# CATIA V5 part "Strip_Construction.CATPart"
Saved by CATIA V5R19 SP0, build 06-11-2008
Part number: Strip_Construction
Bounding box of the stored display mesh (mm): x -31.588 to 851.192, y -98.967 to 61.033, z -30.833 to 220
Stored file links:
  C:\Documents and Settings\drq\Desktop\Final_Data\Strip_Construction.CATPart
  C:\Documents and Settings\drq\Desktop\Final_Data\Worked_Part.CATPart
  C:\Documents and Settings\drq\Desktop\Strip_Construction123.CATPart
  C:\Program Files\Dassault Systemes\Strip Layout Design\intel_a\resources\graphic\Powercopies\PowerCopy_PunchAssociated.CATPart
  C:\Documents and Settings\drq\Desktop\Final_Data\Part_for_Strip.CATPart
  C:\Program Files\Dassault Systemes\Strip Layout Design\intel_a\resources\graphic\Powercopies\ISPSL9UDFCentering.CATPart
  C:\Program Files\Dassault Systemes\Strip Layout Design\intel_a\resources\graphic\Powercopies\UDF-PunchSimulation.CATPart
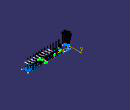
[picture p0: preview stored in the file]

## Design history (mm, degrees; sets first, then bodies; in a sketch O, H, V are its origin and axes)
Parameters
  Step_Length = 55 mm {= External.Step_Length}
  Strip_Width = 120 mm {= External.Strip_Width}
  Nb_Step = 12 {= External.Number_Of_Steps}
  Part_Thickness = 2 mm {= External.Part_Thickness}
  COG_X = 0 mm
  COG_Y = 0 mm
  COG_Z = 0 mm
  group "PunchFoce_Parameters"
    PunchContourArea = 659.1274 mm
    TotalPunchForce = 527302 (force)
    Rupture_Traction_Resistance_Coef = 4e+08 (pressure)
  Station1_FreeStep = 0
  Station2_FreeStep = 0
  Station3_FreeStep = 0
  Station4_FreeStep = 0
  Station5_FreeStep = 0
  Station6_FreeStep = 0
  Station7_FreeStep = 0
  Station8_FreeStep = 0
  Station9_FreeStep = 0
  Station10_FreeStep = 0
External parameters (linked from other documents)
  External.Step_Length = 55 mm
  External.Number_Of_Steps = 12
  External.Strip_Width = 120 mm
  External.Rotation_Part = 60 deg
  External.Part_Thickness = 2 mm
SheetMetalParameters1: BendRadius 4 {= 2*External.Part_Thickness}, ReliefAxialLength 2, ReliefRadialLength 1, MinimumBendRadius 0, Thickness 2 {= External.Part_Thickness}, KFactor 0.400515 {= log(min(100,max(20*SheetMetalParameters1.BendRadius,SheetMetalParameters1.Thickness)/SheetMetalParameters1.Thickness))/log(100)/2}
TTRSSet1
f4a2d38f3ddc11d3a929006094b99c4b_11 "CATTPSSet"
Set1 "Cutting_Step"
  Sketch1 "2Steps_CuttingLine", origin (0, 0, 0), H (1, 0, 0), V (0, 1, 0), geometry linked from another document
  Extrude1 "Main_Extrude": Lim1 5, Lim2 5, Element1 Sketch1
  Translate1 "Cutting_Surface": SecondPoint Translate5, ToTransfor Extrude1, FirstPoint Extremum3
Set2 "SurfacesShadow"
  Extremum1 "Far_Edge": Reference Sketch2
  Extremum2: Reference Sketch2
  Translate2: Distance 160 {= 2*Step_Length+ 50/1000}, ToTransfor Extremum2
  Extremum3 "Ref_Point": Reference Translate2
  Translate3: Distance -55 {= -1*Step_Length}, ToTransfor Extremum2
  Translate4 "Ref_Point: Station- 2": Distance 55 {= (1+Station1_FreeStep)*Step_Length}, ToTransfor Translate3
  Translate5 "Close_Point": Distance 0, ToTransfor Translate13
  Translate6 "Ref_Point: Station- 3": Distance 55 {= (1+Station2_FreeStep)*Step_Length}, ToTransfor Translate4
  Translate7 "Ref_Point: Station- 4": Distance 55 {= (1+Station3_FreeStep)*Step_Length}, ToTransfor Translate6
  Translate8 "Ref_Point: Station- 5": Distance 55 {= (1+Station4_FreeStep)*Step_Length}, ToTransfor Translate7
  Translate9 "Ref_Point: Station- 6": Distance 55 {= (1+Station5_FreeStep)*Step_Length}, ToTransfor Translate8
  Translate10 "Ref_Point: Station- 7": Distance 55 {= (1+Station6_FreeStep)*Step_Length}, ToTransfor Translate9
  Translate11 "Ref_Point: Station- 8": Distance 55 {= (1+Station7_FreeStep)*Step_Length}, ToTransfor Translate10
  Translate12 "Ref_Point: Station- 9": Distance 55 {= (1+Station8_FreeStep)*Step_Length}, ToTransfor Translate11
  Translate13 "Ref_Point: Station- 10": Distance 55 {= (1+Station9_FreeStep)*Step_Length}, ToTransfor Translate12
Set3 "PositioningPunches"
  Translate14 "LeadFrame_Contour": Length 0, Direction (1, 0, 0)
  Translate15 "Punch_Contour: Station1": Distance -55 {= -1*Step_Length}, ToTransfor Translate24
  Translate16 "Punch_Contour: Station3:3rd": Distance -55 {= -1*Step_Length}, ToTransfor Translate29
  Translate17 "Punch_Contour: Station6:6th": Distance -55 {= -1*Step_Length}, ToTransfor Translate35
  Translate18 "Punch_Contour: Station7:7th": Distance -55 {= -1*Step_Length}, ToTransfor Translate39
  Translate19 "Punch_Contour: Station8:8th": Distance -55 {= -1*Step_Length}, ToTransfor Translate43
  Translate20 "Punch_Contour: Station8:8th": Distance -55 {= -1*Step_Length}, ToTransfor Translate46
  Translate21 "Punch_Contour: Station9:9th": Distance -55 {= -1*Step_Length}, ToTransfor Translate50
Set4 "References_From_Worked_Part"
  Sketch2 "BoundaryStrip", origin (0, 0, 0), H (1, 0, 0), V (0, 1, 0), geometry linked from another document
  DatumCurve1 to DatumCurve7 "PunchBoundary": linked copy from another document
  Line1: linked copy from another document
Set5 "Punch_Force_Calculation"
  Join1 "PunchContour": Elements (Circle1; Translate24; Translate29; Trim3; Trim4; Translate43; Translate46; Translate50)
  Circle1 "Ref_Contour_PunchForce": type CtrRad, Start 0, End 180, Support xy-plane, Center {point type OnPlane, Support xy-plane, Direction (1, 0, 0), H 88.519, V 119.312}, Radius 5, FirstDirection (1, 0, 0)
Set6 "Punch.1"
  Fill1: Boundary Translate15
  Extrude2: Punch Translate24, Lim1 100, Lim2 0, Element1 Fill1
Set7 "Punch.2"
  Fill2: Boundary Translate16
  Extrude3: Punch Translate29, Lim1 100, Lim2 0, Element1 Fill2
Set8 "Punch.3"
  Fill3: Boundary Translate17
  Extrude4: Punch Trim3, Lim1 100, Lim2 0, Element1 Fill3
Set9 "Punch.4"
  Fill4: Boundary Translate18
  Extrude5: Punch Trim4, Lim1 100, Lim2 0, Element1 Fill4
Set10 "Punch.5"
  Fill5: Boundary Translate19
  Extrude6: Punch Translate43, Lim1 100, Lim2 0, Element1 Fill5
Set11 "Punch.6"
  Fill6: Boundary Translate20
  Extrude7: Punch Translate46, Lim1 100, Lim2 0, Element1 Fill6
Set12 "Punch.7"
  Fill7: Boundary Translate21
  Extrude8: Punch Translate50, Lim1 100, Lim2 0, Element1 Fill7
Body1 (main body)
  Body2 "Step0"
    Solid1: CATSmSolid_Thickness 2 {= External.Part_Thickness}, linked copy from another document
    Translate22: Distance 160 {= 2*Step_Length+ 50/1000}
  Assemble1 "None_Station": tool Body2
  Body3 "Step1(Result_Of_Step0)"
    Solid2: CATSmSolid_Thickness 2 {= External.Part_Thickness}, linked copy from another document
    Translate23: Distance 55 {= Step_Length}
    Translate24: SecondPoint Translate3, ToTransfor DatumCurve3, FirstPoint Extremum3
    Trim1: Trimmed (Translate24; Sketch2)
    Translate25: ToTransfor Trim1
    Wall1: ListTangentTo Translate23, Thickness 2 {= External.Part_Thickness}, Profile Translate25
    Translate26: Length -55 {= -1*Step_Length}, Direction (1, 0, 0), ToTransfor Translate25
    CutOut1: StartLimit through (limit type 2), Orientation false, Profile Translate26, Direction Translate26, EndLimit through (limit type 2), deactivated
  Assemble2 "Station1": tool Body3
  RectPattern1: of Body3, direction 1 instances 1 {= Station1_FreeStep+1}, spacing 55 {= Step_Length}, along xy-plane, deactivated
  Body4 "Step1(Result_Of_Step0)"
    Solid3: CATSmSolid_Thickness 2 {= External.Part_Thickness}, linked copy from another document
    Translate27: Distance 55 {= (1+Station1_FreeStep)*Step_Length}
    Unfold1: FoldUnfold_ReferenceFaces face of Solid3, FoldUnfold_Angle 45, FoldUnfold_Angle 45, FoldUnfold_Angle 45, FoldUnfold_Angle 45, FoldUnfold_FoldUnfoldFaces (face of Solid3; face of Solid3; face of Solid3; face of Solid3)
    Sketch3 on face of Solid3, origin (-562.6458, 177.1813, 0), H (-0.3556, 0.9346, 0), V (0.9346, 0.3556, 0)
      projected arc E1 centre (-463.5079, 703.8938) radius 4.899 from (-468.3443, 704.6746) to (-458.6716, 703.113) ccw from edge [face of Solid3 | face of Solid3]
      projected line E2 (-456.2415, 718.1654) -> (-455.8093, 720.8426) from edge [face of Solid3 | face of Solid3]
      projected line E3 (-456.8425, 714.4428) -> (-456.2415, 718.1654) from edge [face of Solid3 | face of Solid3]
      projected line E4 (-455.8023, 720.8865) -> (-455.2084, 724.5652) from edge [face of Solid3 | face of Solid3]
      projected line E5 (-456.8425, 714.4428) -> (-458.6716, 703.113) from edge [face of Solid3 | face of Solid3]
      projected line E6 (-466.5152, 716.0044) -> (-468.3443, 704.6746) from edge [face of Solid3 | face of Solid3]
      projected line E7 (-466.5152, 716.0044) -> (-465.9143, 719.7269) from edge [face of Solid3 | face of Solid3]
      projected line E8 (-465.9143, 719.7269) -> (-465.4821, 722.4042) from edge [face of Solid3 | face of Solid3]
      projected line E9 (-465.475, 722.448) -> (-464.8811, 726.1267) from edge [face of Solid3 | face of Solid3]
      projected line E10 (-464.8811, 726.1267) -> (-464.1622, 730.5797) from edge [face of Solid3 | face of Solid3]
      projected arc E11 centre (-459.3258, 729.7989) radius 4.899 from (-454.4895, 729.0182) to (-464.1622, 730.5797) ccw from edge [face of Solid3 | face of Solid3]
      projected line E12 (-454.4895, 729.0182) -> (-455.2084, 724.5651) from edge [face of Solid3 | face of Solid3]
      projected line E13 (-455.8023, 720.8865) -> (-455.8093, 720.8426) from edge [face of Solid3 | face of Solid3]
      projected line E14 (-465.475, 722.448) -> (-465.4821, 722.4042) from edge [face of Solid3 | face of Solid3]
    Wall2: ListTangentTo Translate27, Thickness 2 {= External.Part_Thickness}, Profile Sketch3
  Assemble3 "Station2:2nd": tool Body4
  RectPattern2 "Pattern.Station2:2nd": of Body4, direction 1 instances 1 {= Station2_FreeStep+1}, spacing 55 {= Step_Length}, along xy-plane, deactivated
  Body5 "Step1(Result_Of_Step0)"
    Solid4: CATSmSolid_Thickness 2 {= External.Part_Thickness}, linked copy from another document
    Translate28: Distance 55 {= (1+Station2_FreeStep)*Step_Length}
    Translate29: SecondPoint Translate6, ToTransfor DatumCurve2, FirstPoint Extremum3
    Trim2: Trimmed (Translate29; Sketch2)
    Translate30: ToTransfor Trim2
    Wall3: ListTangentTo Translate28, Thickness 2 {= External.Part_Thickness}, Profile Translate30
    Translate31: Length -55 {= -1*Step_Length}, Direction (1, 0, 0), ToTransfor Translate30
    CutOut2: StartLimit through (limit type 2), Orientation false, Profile Translate31, Direction Translate31, EndLimit through (limit type 2), deactivated
  Assemble4 "Station3:3rd": tool Body5
  RectPattern3 "Pattern.Station3:3rd": of Body5, direction 1 instances 1 {= Station3_FreeStep+1}, spacing 55 {= Step_Length}, along xy-plane, deactivated
  Body6 "Step1(Result_Of_Step0)"
    Solid5: CATSmSolid_Thickness 2 {= External.Part_Thickness}, linked copy from another document
    Translate32: Distance 55 {= (1+Station3_FreeStep)*Step_Length}
    Unfold2: FoldUnfold_ReferenceFaces face of Solid5, FoldUnfold_Angle 92.84, FoldUnfold_Angle 92.84, FoldUnfold_FoldUnfoldFaces (face of Solid5; face of Solid5)
    Sketch4 on face of Solid5, origin (-562.6458, 177.1813, 0), H (-0.3556, 0.9346, 0), V (0.9346, 0.3556, 0)
      projected arc E1 centre (-524.8364, 776.7988) radius 3.6056 from (-525.541, 773.2628) to (-524.1318, 780.3349) ccw from edge [face of Solid5 | face of Solid5]
      projected line E2 (-526.3434, 780.7756) -> (-524.1318, 780.3349) from edge [face of Solid5 | face of Solid5]
      projected line E3 (-533.9728, 782.2959) -> (-526.3434, 780.7756) from edge [face of Solid5 | face of Solid5]
      projected line E4 (-533.9728, 782.2959) -> (-535.7603, 782.6521) from edge [face of Solid5 | face of Solid5]
      projected arc E5 centre (-536.4649, 779.1161) radius 3.6056 from (-535.7603, 782.6521) to (-537.1696, 775.5801) ccw from edge [face of Solid5 | face of Solid5]
      projected line E6 (-537.1696, 775.5801) -> (-535.3821, 775.2239) from edge [face of Solid5 | face of Solid5]
      projected line E7 (-535.3821, 775.2239) -> (-527.7527, 773.7035) from edge [face of Solid5 | face of Solid5]
      projected line E8 (-527.7527, 773.7035) -> (-525.541, 773.2628) from edge [face of Solid5 | face of Solid5]
    Wall4: ListTangentTo Translate32, Thickness 2 {= External.Part_Thickness}, Profile Sketch4
  Assemble5 "Station4:4th": tool Body6
  RectPattern4 "Pattern.Station4:4th": of Body6, direction 1 instances 1 {= Station4_FreeStep+1}, spacing 55 {= Step_Length}, along xy-plane, deactivated
  Body7 "Step1(Result_Of_Step0)"
    Solid6: CATSmSolid_Thickness 2 {= External.Part_Thickness}, linked copy from another document
    Translate33: Distance 55 {= (1+Station4_FreeStep)*Step_Length}
    Unfold3: FoldUnfold_ReferenceFaces face of Solid6, FoldUnfold_Angle 90, FoldUnfold_Angle 90, FoldUnfold_FoldUnfoldFaces (face of Solid6; face of Solid6)
    Sketch5 on face of Solid6, origin (307.1206, 575.8562, 0.0003), H (0.6316, 0.7753, 0), V (0.7753, -0.6316, 0)
      projected curve E1 from edge [face of Solid6 | face of Solid6]
      projected arc E2 centre (-439.6905, 486.546) radius 29.1687 from (-410.8694, 482.0568) to (-410.6817, 489.5959) ccw from edge [face of Solid6 | face of Solid6]
      projected curve E3 from edge [face of Solid6 | face of Solid6]
      projected arc E4 centre (-393.8831, 485.406) radius 29.1659 from (-422.7015, 489.895) to (-422.8891, 482.3559) ccw from edge [face of Solid6 | face of Solid6]
    Wall5: ListTangentTo Translate33, Thickness 2 {= External.Part_Thickness}, Profile Sketch5
  Assemble6 "Station5:5th": tool Body7
  RectPattern5 "Pattern.Station5:5th": of Body7, direction 1 instances 1 {= Station5_FreeStep+1}, spacing 55 {= Step_Length}, along xy-plane, deactivated
  Body8 "Step1(Result_Of_Step0)"
    Solid7: CATSmSolid_Thickness 2 {= External.Part_Thickness}, linked copy from another document
    Translate34: Distance 55 {= (1+Station5_FreeStep)*Step_Length}
    Translate35: SecondPoint Translate9, ToTransfor DatumCurve1, FirstPoint Extremum3
    Trim3: Trimmed (Translate35; Sketch2)
    Translate36: ToTransfor Trim3
    Wall6: ListTangentTo Translate34, Thickness 2 {= External.Part_Thickness}, Profile Translate36
    Translate37: Length -55 {= -1*Step_Length}, Direction (1, 0, 0), ToTransfor Translate36
    CutOut3: StartLimit through (limit type 2), Orientation false, Profile Translate37, Direction Translate37, EndLimit through (limit type 2)
  Assemble7 "Station6:6th": tool Body8
  RectPattern6 "Pattern.Station6:6th": of Body8, direction 1 instances 1 {= Station6_FreeStep+1}, spacing 55 {= Step_Length}, along xy-plane, deactivated
  Body9 "Step1(Result_Of_Step0)"
    Solid8: CATSmSolid_Thickness 2 {= External.Part_Thickness}, linked copy from another document
    Translate38: Distance 55 {= (1+Station6_FreeStep)*Step_Length}
    Translate39: SecondPoint Translate10, ToTransfor DatumCurve4, FirstPoint Extremum3
    Trim4: Trimmed (Translate39; Sketch2)
    Translate40: ToTransfor Trim4
    Wall7: ListTangentTo Translate38, Thickness 2 {= External.Part_Thickness}, Profile Translate40
    Translate41: Length -55 {= -1*Step_Length}, Direction (1, 0, 0), ToTransfor Translate40
    CutOut4: StartLimit through (limit type 2), Orientation false, Profile Translate41, Direction Translate41, EndLimit through (limit type 2)
  Assemble8 "Station7:7th": tool Body9
  RectPattern7 "Pattern.Station7:7th": of Body9, direction 1 instances 1 {= Station7_FreeStep+1}, spacing 55 {= Step_Length}, along xy-plane, deactivated
  Body10 "Step1(Result_Of_Step0)"
    Solid9: CATSmSolid_Thickness 2 {= External.Part_Thickness}, linked copy from another document
    Translate42: Distance 55 {= (1+Station7_FreeStep)*Step_Length}
    Translate43: SecondPoint Translate11, ToTransfor DatumCurve5, FirstPoint Extremum3
    Trim5: Trimmed (Translate43; Sketch2)
    Translate44: ToTransfor Trim5
    Wall8: ListTangentTo Translate42, Thickness 2 {= External.Part_Thickness}, Profile Translate44
    Translate45: Length -55 {= -1*Step_Length}, Direction (1, 0, 0), ToTransfor Translate44
    CutOut5: StartLimit through (limit type 2), Orientation false, Profile Translate45, Direction Translate45, EndLimit through (limit type 2), deactivated
    Translate46: SecondPoint Translate11, ToTransfor DatumCurve6, FirstPoint Extremum3
    Trim6: Trimmed (Translate46; Sketch2)
    Translate47: ToTransfor Trim6
    Wall9: ListTangentTo Translate42, Thickness 2 {= External.Part_Thickness}, Profile Translate47
    Translate48: Length -55 {= -1*Step_Length}, Direction (1, 0, 0), ToTransfor Translate47
    CutOut6: StartLimit through (limit type 2), Orientation false, Profile Translate48, Direction Translate48, EndLimit through (limit type 2), deactivated
  Assemble9 "Station8:8th": tool Body10
  RectPattern8 "Pattern.Station8:8th": of Body10, direction 1 instances 1 {= Station8_FreeStep+1}, spacing 55 {= Step_Length}, along xy-plane, deactivated
  Body11 "Step1(Result_Of_Step0)"
    Solid10: CATSmSolid_Thickness 2 {= External.Part_Thickness}, linked copy from another document
    Translate49: Distance 55 {= (1+Station8_FreeStep)*Step_Length}
    Translate50: SecondPoint Translate12, ToTransfor DatumCurve7, FirstPoint Extremum3
    Trim7: Trimmed (Translate50; Sketch2)
    Translate51: ToTransfor Trim7
    Wall10: ListTangentTo Translate49, Thickness 2 {= External.Part_Thickness}, Profile Translate51
    Translate52: Length -55 {= -1*Step_Length}, Direction (1, 0, 0), ToTransfor Translate51
    CutOut7: StartLimit through (limit type 2), Orientation false, Profile Translate52, Direction Translate52, EndLimit through (limit type 2), deactivated
  Assemble10 "Station9:9th": tool Body11
  RectPattern9 "Pattern.Station9:9th": of Body11, direction 1 instances 1 {= Station9_FreeStep+1}, spacing 55 {= Step_Length}, along xy-plane, deactivated
  Body12 "Step1(Result_Of_Step0)"
    Solid11: CATSmSolid_Thickness 2 {= External.Part_Thickness}, linked copy from another document
    Translate53: Distance 55 {= (1+Station9_FreeStep)*Step_Length}
  Assemble11 "Station10:10th": tool Body12
  RectPattern10 "Pattern.Station10:10th": of Body12, direction 1 instances 1 {= Station10_FreeStep+1}, spacing 55 {= Step_Length}, along xy-plane, deactivated
  Body13 "StartingStep"
    Extremum4: Reference Sketch2
    Extremum5: Reference Sketch2
    Line2: type PtPt, SecondPoint Extremum5, FirstPoint Extremum4
    Extrude9: Lim1 35, Lim2 -55 {= -1000*Step_Length}, FirstUpto Translate1, Element1 Line2
    ThickSurface1: Surface Extrude9, BotOffset 0, TopOffset 2 {= Part_Thickness}
    Extremum6: Reference Extrude9
    Extremum7: Reference Extrude9
    Extremum8: Reference Extrude9
  Assemble12: tool Body13
  Body14 "CloseStep"
    Sketch6 on xy-plane, origin (0, 0, 0), H (1, 0, 0), V (0, 1, 0)
      line L1 (851.192, 41.0329) -> (851.192, -78.9671)
      line L2 (851.192, -78.9671) -> (906.192, -78.9671)
      line L3 (906.192, -78.9671) -> (906.192, 41.0329)
      line L4 (906.192, 41.0329) -> (851.192, 41.0329)
      reference projected line E1 (851.192, -78.9671) -> (851.192, 41.0329) from Line2
      reference projected line E2 (906.192, -78.9671) -> (906.192, 41.0329) from Extremum8
      reference projected line E3 (906.192, 41.0329) -> (775.833, 41.0329) from Extremum7
      reference projected line E4 (906.192, -78.9671) -> (706.5509, -78.9671) from Extremum6
      coincidence: L1 E1, L2 E4, L3 E2, L4 E3
    Pocket1: profile Sketch6, direction (0, 0, -1), length 20, mirrored extent
  Assemble13: tool Body14
  Body15 "TempBody"
  Remove1 "End Of Strip": tool Body15
  UdfFeature1 "PilotSlots_Auto": UdfShapeIn Remove1, UdfInputSpec1 {plane1curve Element1 Sketch2}, UdfInputSpec2 Extremum9, UdfInputSpec3 Extremum10, UdfInputSpec4 {planeoffset Offset 0, RefPlane xy-plane}
Body16 "Isolated"
  Solid12: linked copy from another document
  Rotate1: Axis Line1, Angle 60, ToTransfor Solid12
  Translate54: Distance 160 {= 2*Step_Length+ 50/1000}, ToTransfor Rotate1
  RectPattern11: of Translate54, direction 1 instances 4, spacing 55 {= Step_Length}, along xy-plane
Body17 "Isolated"
  Solid13: linked copy from another document
  Rotate2: Axis Line1, Angle 60, ToTransfor Solid13
  Translate55: Distance 160 {= 2*Step_Length+ 50/1000}, ToTransfor Rotate2
  RectPattern12: of Translate55, direction 1 instances 4, spacing 55 {= Step_Length}, along xy-plane
Body18 "Isolated"
  Solid14: linked copy from another document
  Rotate3: Axis Line1, Angle 60, ToTransfor Solid14
  Translate56: Distance 160 {= 2*Step_Length+ 50/1000}, ToTransfor Rotate3
  RectPattern13: of Translate56, direction 1 instances 2, spacing 55 {= Step_Length}, along xy-plane
Body19 "Isolated"
  Solid15: linked copy from another document
  Translate57: SecondPoint vertex [face of Solid5 | face of Solid5 | face of Solid5 | face of Solid5], ToTransfor Solid15, FirstPoint vertex [face of Solid15 | face of Solid15 | face of Solid15 | face of Solid15]
  Rotate4: Point1 vertex [face of Solid15 | face of Solid15 | face of Solid15 | face of Solid15], Point2 vertex [face of Solid5 | face of Solid5 | face of Solid5 | face of Solid5], Point3 vertex [face of Solid5 | face of Solid5 | face of Solid5 | face of Solid5], ToTransfor Translate57
  Rotate5: Axis {line type PtPt, SecondPoint vertex [face of Solid5 | face of Solid5 | face of Solid5 | face of Solid5], FirstPoint vertex [face of Solid5 | face of Solid5 | face of Solid5 | face of Solid5]}, Element1 vertex [face of Solid15 | face of Solid15 | face of Solid15 | face of Solid15], Element2 vertex [face of Solid5 | face of Solid5 | face of Solid5 | face of Solid5], ToTransfor Rotate4
Body20 "CenteringToolAuto"
  UdfFeature2 "Pilots_Auto": UdfComponents ({plane type 1Curve, Element1 Sketch2}; {plane type Offset, Offset -8, RefPlane {plane type 1Curve, Element1 Sketch2}}; {plane type Offset, Offset 10, RefPlane {plane type Offset, Offset -8, RefPlane {plane type 1Curve, Element1 Sketch2}}}; {plane type Offset, Offset 200, RefPlane {plane type Offset, Offset -8, RefPlane {plane type 1Curve, Element1 Sketch2}}}; {extremum Reference Sketch2, Direction2 (0, 0, 1), Direction3 (0, 0, 1), Direction (1, 0, 0)}; {extremum Reference Sketch2, Direction2 (0, 0, 1), Direction3 (0, 0, 1), Direction (0, 1, 0)}; a sketch; {loft Sections (a sketch; a sketch; a sketch)}), UdfInputSpec1 {plane1curve Element1 Sketch2}, UdfInputSpec4 {planeoffset Offset 0, RefPlane xy-plane}
Body21 "Punch"
  UdfFeature3 "Punch_HeadBox": UdfComponents Body26, UdfInputSpec1 Fill8, Punch_HeadBox_Hight 200, Punch_HeadBox_Head_Hight 20, Punch_HeadBox_Offset 10, UdfOutputs CloseSurface1
Body22 "Punch"
  UdfFeature4 "Punch_HeadBox": UdfComponents Body27, UdfInputSpec1 Fill11, Punch_HeadBox_Hight 200, Punch_HeadBox_Head_Hight 20, Punch_HeadBox_Offset 10, UdfOutputs CloseSurface2
Body23 "Punch"
  UdfFeature5 "Punch_HeadCircular": UdfComponents Body28, UdfInputSpec1 Fill14, Punch_HeadCircular_Hight 100, Punch_HeadCircular_Head_Hight 20, Punch_HeadCircular_Offset 10, UdfOutputs CloseSurface3
Body24 "Punch"
  UdfFeature6 "Punch_HeadOffset": UdfComponents Body29, UdfInputSpec1 Fill17, UdfInputSpec2 Extrude16, Punch_HeadOffset_Hight 200, Punch_HeadOffset_Head_Hight 20, Punch_HeadOffset_Offset 10, UdfOutputs CloseSurface4
Body25 "CenteringAuto"
  Plane1: type 1Curve, Element1 Sketch2
  Plane2: type Offset, Offset -8, RefPlane Plane1
  Plane3: type Offset, Offset 10, RefPlane Plane2
  Plane4: type Offset, Offset 200, RefPlane Plane2
  Extremum9 "Copy (3) of ExtremXmin": Reference Sketch2, Direction2 (0, 0, 1), Direction3 (0, 0, 1), Direction (1, 0, 0)
  Extremum10 "Copy (3) of ExtremYmin": Reference Sketch2, Direction2 (0, 0, 1), Direction3 (0, 0, 1), Direction (0, 1, 0)
  Sketch7 on Plane3, origin (0, 0, 2), H (1, 0, 0), V (0, 1, 0)
    circle A1 centre (796.192, -18.9671) radius 3.5
    point P1 (796.192, -18.9671)
    reference projected line E1 (136.192, -78.9671) -> (851.192, -78.9671) from Extremum10
    reference projected line E2 (851.192, -78.9671) -> (851.192, 41.0329) from Extremum9
    radius A1 = 3.5 {= UdfFeature1.Centering_Diameter /2}
    distance E1 P1 = 60 {= UdfFeature1.Centering_Ypos}
    distance P1 E2 = 55 {= UdfFeature1.Centering_Xpos}
  Sketch8 on Plane2, origin (0, 0, -8), H (1, 0, 0), V (0, 1, 0)
    circle A1 centre (796.192, -18.9671) radius 1.1667
    reference projected circle E1 centre (796.192, -18.9671) radius 3.5 from Sketch7.A1
    radius A1 = 1.1667 {= UdfFeature1.Centering_Diameter /6}
    concentricity: A1 E1
  Sketch9 on Plane4, origin (0, 0, 192), H (1, 0, 0), V (0, 1, 0)
    circle A1 centre (796.192, -18.9671) radius 3.4759
    reference projected circle E1 centre (796.192, -18.9671) radius 1.1667 from Sketch8.A1
    radius A1 = 3.4759
    concentricity: A1 E1
  Loft1: solid, Sections (Sketch8; Sketch7; Sketch9)
  RectPattern14: of Loft1, direction 1 instances 12, spacing 55 {= Step_Length}, along {plane type Offset, Offset 0, RefPlane xy-plane} reversed
Body26 "Punch_HeadBox"
  Fill8: Boundary DatumCurve1
  Boundary1: Boundary Fill8
  Extrude10: Punch_HeadBox_Hight 200, Lim2 0, Element1 Boundary1, Direction Fill8
  Join2: Elements (Extrude10; Fill8)
  Boundary2: Boundary Join2
  Extremum11: Reference Boundary2, Direction2 (0, 1, 0), Direction3 (0, 0, 1), Direction (1, 0, 0)
  Extremum12: Reference Boundary2, Direction2 (0, 1, 0), Direction3 (0, 0, 1), Direction (1, 0, 0)
  Extremum13: Reference Boundary2, Direction2 (1, 0, 0), Direction3 (0, 0, 1), Direction (0, 1, 0)
  Extremum14: Reference Boundary2, Direction2 (1, 0, 0), Direction3 (0, 0, 1), Direction (0, 1, 0)
  Fill9: Boundary Boundary2
  Sketch10 on Fill9, origin (97.5694, 38.0387, 200), H (1, 0, 0), V (0, -1, 0)
    line L1 (-56.3737, 27.5269) -> (0, 27.5269)
    line L2 (0, 27.5269) -> (0, -12.9942)
    line L3 (0, -12.9942) -> (-56.3737, -12.9942)
    line L4 (-56.3737, -12.9942) -> (-56.3737, 27.5269)
    reference projected point E1 (-5, -12.9942) from Extremum13
    reference projected point E2 (0, 0) from Extremum11
    reference projected point E3 (-50.3623, 27.5269) from Extremum14
    reference projected point E4 (-56.3737, -7.9942) from Extremum12
    horizontal: L1 H, L3 H
    vertical: L2 V, L4 V
    coincidence: L3 E1, L2 E2, L1 E3, L4 E4
  CurvePar1: Punch_HeadBox_Offset 10, Offset2 0, Offset Sketch10
  Fill10: Boundary CurvePar1
  Split1: ToCut Fill10, Cutting Boundary2
  Extrude11: Punch_HeadBox_Head_Hight 20, Lim2 0, Element1 CurvePar1, Direction Fill9
  Join3: Elements (Extrude11; Split1; Join2)
  CloseSurface1: CloseElement Join3
Body27 "Punch_HeadBox"
  Fill11: Boundary DatumCurve2
  Boundary3: Boundary Fill11
  Extrude12: Punch_HeadBox_Hight 200, Lim2 0, Element1 Boundary3, Direction Fill11
  Join4: Elements (Extrude12; Fill11)
  Boundary4: Boundary Join4
  Extremum15: Reference Boundary4, Direction2 (0, 1, 0), Direction3 (0, 0, 1), Direction (1, 0, 0)
  Extremum16: Reference Boundary4, Direction2 (0, 1, 0), Direction3 (0, 0, 1), Direction (1, 0, 0)
  Extremum17: Reference Boundary4, Direction2 (1, 0, 0), Direction3 (0, 0, 1), Direction (0, 1, 0)
  Extremum18: Reference Boundary4, Direction2 (1, 0, 0), Direction3 (0, 0, 1), Direction (0, 1, 0)
  Fill12: Boundary Boundary4
  Sketch11 on Fill12, origin (47.4674, 10.6622, 200), H (1, 0, 0), V (0, -1, 0)
    line L1 (-45.7348, 24.673) -> (0, 24.673)
    line L2 (0, 24.673) -> (0, -4.3797)
    line L3 (0, -4.3797) -> (-45.7348, -4.3797)
    line L4 (-45.7348, -4.3797) -> (-45.7348, 24.673)
    reference projected point E1 (-2.9345, -4.3797) from Extremum17
    reference projected point E2 (0, 0) from Extremum15
    reference projected point E3 (-45.7348, 24.673) from Extremum18
    reference projected point E4 (-45.7348, 24.673) from Extremum16
    horizontal: L1 H, L3 H
    vertical: L2 V, L4 V
    coincidence: L3 E1, L2 E2, L1 E3, L4 E4
  CurvePar2: Punch_HeadBox_Offset 10, Offset2 0, Offset Sketch11
  Fill13: Boundary CurvePar2
  Split2: ToCut Fill13, Cutting Boundary4
  Extrude13: Punch_HeadBox_Head_Hight 20, Lim2 0, Element1 CurvePar2, Direction Fill12
  Join5: Elements (Extrude13; Split2; Join4)
  CloseSurface2: CloseElement Join5
Body28 "Punch_HeadCircular"
  Fill14: Boundary DatumCurve3
  Boundary5: Boundary Fill14
  Extrude14: Punch_HeadCircular_Hight 100, Lim2 0, Element1 Boundary5, Direction Fill14
  Join6: Elements (Extrude14; Fill14)
  Boundary6: Boundary Join6
  Extremum19: Reference Boundary6, Direction2 (0, 1, 0), Direction3 (0, 0, 1), Direction (1, 0, 0)
  Extremum20: Reference Boundary6, Direction2 (0, 1, 0), Direction3 (0, 0, 1), Direction (1, 0, 0)
  Extremum21: Reference Boundary6, Direction2 (1, 0, 0), Direction3 (0, 0, 1), Direction (0, 1, 0)
  Extremum22: Reference Boundary6, Direction2 (1, 0, 0), Direction3 (0, 0, 1), Direction (0, 1, 0)
  Fill15: Boundary Boundary6
  Sketch12 on Fill15, origin (21.0967, -13.7108, 100), H (1, 0, 0), V (0, -1, 0)
    line L1 (-40.7573, 17.511) -> (0, 17.511)
    line L2 (0, 17.511) -> (0, 0)
    line L3 (0, 0) -> (-40.7573, 0)
    line L4 (-40.7573, 0) -> (-40.7573, 17.511)
    reference projected point E1 (0, 0) from Extremum21
    reference projected point E2 (-40.5927, 17.511) from Extremum22
    reference projected point E3 (0, 0) from Extremum19
    reference projected point E4 (-40.7573, 16.1155) from Extremum20
    horizontal: L1 H, L3 H
    vertical: L2 V, L4 V
    coincidence: L3 E1, L1 E2, L2 E3, L4 E4
  CurvePar3: Punch_HeadCircular_Offset 10, Offset2 0, Offset Sketch12
  Extract1: ExtractElem edge of CurvePar3
  Extract2: ExtractElem edge of CurvePar3
  Extract3: ExtractElem edge of CurvePar3
  Extract4: ExtractElem edge of CurvePar3
  Sketch13 on Fill15, origin (21.0967, -13.7108, 100), H (1, 0, 0), V (0, -1, 0)
    reference projected line E1 (-50.7573, -10) -> (10, -10) from edge of CurvePar3
    reference projected line E2 (10, -10) -> (10, 27.511) from edge of CurvePar3
    reference projected line E3 (10, 27.511) -> (-50.7573, 27.511) from edge of CurvePar3
    reference projected line E4 (-50.7573, 27.511) -> (-50.7573, -10) from edge of CurvePar3
    construction circle A1 centre (-8.7555, 8.7555) radius 18.7555
    construction circle A2 centre (-32.0018, 8.7555) radius 18.7555
    construction line L1 (-32.0018, 8.7555) -> (-8.7555, 8.7555)
    point P11 (-20.3786, 23.4753)
    point P12 (-20.3786, -5.9643)
    construction line L2 (-20.3786, 23.4753) -> (-20.3786, -5.9643)
    point P13 (-20.3786, 8.7555)
    circle A3 centre (-20.3786, 8.7555) radius 30.3786
    tangency: A1 E3, A1 E2, A1 E1, A2 E4, A2 E1, A2 E3, A3 E2
    coincidence: A1 P11, A2 P11, A1 P12, A2 P12, L1 P13, L2 P13
  Fill16: Boundary Sketch13
  Split3: ToCut Fill16, Cutting Boundary6
  Extrude15: Punch_HeadCircular_Head_Hight 20, Lim2 0, Element1 Sketch13, Direction Fill15
  Join7: Elements (Extrude15; Split3; Join6)
  CloseSurface3: CloseElement Join7
Body29 "Punch_HeadOffset"
  Fill17: Boundary DatumCurve4
  Extrude16: Punch_HeadOffset_Hight 200, Lim2 0, Element1 DatumCurve4, Direction Fill17
  Join8: Elements (Fill17; Extrude16)
  Boundary7: Boundary Join8
  CurvePar4: Punch_HeadOffset_Offset 10, Offset2 0, Offset Boundary7
  Fill18: Boundary CurvePar4
  Split4: ToCut Fill18, Cutting Boundary7
  Extrude17: Punch_HeadOffset_Head_Hight 20, Lim2 0, Element1 CurvePar4, Direction Split4
  Join9: Elements (Join8; Split4)
  Join10: Elements (Join9; Extrude17)
  CloseSurface4: CloseElement Join10
Relations
   = Body1 .Query("Pattern","")
   = Set5.Query("UserFeature","")
  rule:
    /*Rule created by DRQ 7/9/2008*/
    PunchContourArea = length(Join1)-length(Circle1)
  rule:
    /*Rule created by DRQ 7/9/2008*/
    TotalPunchForce =PunchContourArea *Rupture_Traction_Resistance_Coef *External.Part_Thickness
  Pocket1.ThickThin1 = Part_Thickness
  UdfFeature2.Centering_Xpos = UdfFeature1.Centering_Xpos
  UdfFeature2.Centering_Ypos = UdfFeature1.Centering_Ypos
  UdfFeature2.Centering_Diameter = UdfFeature1.Centering_Diameter
  UdfFeature2.Centering_Xpos = UdfFeature1.Centering_Xpos (deactivated)
  UdfFeature2.Centering_Ypos = UdfFeature1.Centering_Ypos (deactivated)
  UdfFeature2.Centering_Diameter = UdfFeature1.Centering_Diameter (deactivated)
